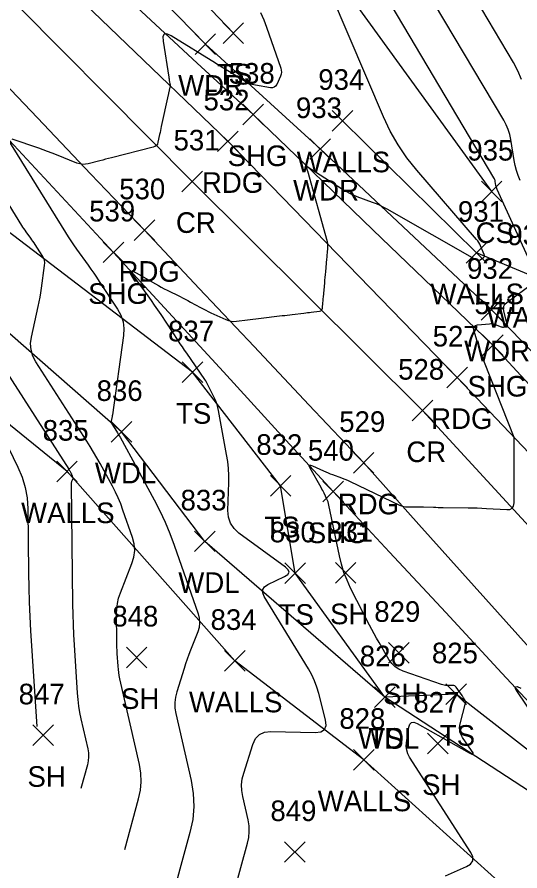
# Model space of a CAD drawing. Extents: x 1592612 to 1596497, y 111838 to 113741.
# Drawn here: x 1592673.5 to 1592722.3, y 113548.4 to 113631.2 of the extents above; entities that cross this region are included whole.
import ezdxf

# ---------------------------------------------------------------- set-up
doc = ezdxf.new("R2010")
doc.units = 0
for name, color, linetype in [('L_A', 7, 'Continuous'), ('L_I', 7, 'Continuous'), ('L_TIC', 7, 'Continuous'), ('LAWA', 7, 'Continuous'), ('LELB', 7, 'Continuous'), ('LSOGCMA', 7, 'Continuous'), ('LSOGCMI', 7, 'Continuous'), ('LWS', 7, 'Continuous'), ('P_A', 7, 'Continuous'), ('P_I', 7, 'Continuous'), ('P_TIC', 7, 'Continuous'), ('PEU', 7, 'Continuous'), ('PRC', 7, 'Continuous'), ('PSU', 7, 'Continuous')]:
    doc.layers.add(name, color=color, linetype=linetype)

msp = doc.modelspace()

# ---------------------------------------------------------------- linework, layer by layer
at = {"layer": 'L_TIC'}
for points in [[(1592693.494, 113628.695), (1592695.494, 113630.695)], [(1592695.494, 113628.695), (1592693.494, 113630.695)], [(1592690.78, 113627.612), (1592692.78, 113629.612)], [(1592692.78, 113627.612), (1592690.78, 113629.612)], [(1592704.094, 113620.183), (1592706.094, 113622.183)], [(1592706.094, 113620.183), (1592704.094, 113622.183)], [(1592701.926, 113617.445), (1592703.926, 113619.445)], [(1592703.926, 113617.445), (1592701.926, 113619.445)], [(1592718.548, 113613.319), (1592720.548, 113615.319)], [(1592720.548, 113613.319), (1592718.548, 113615.319)], [(1592717.067, 113607.381), (1592719.067, 113609.381)], [(1592719.067, 113607.381), (1592717.067, 113609.381)], [(1592718.52, 113601.847), (1592720.52, 113603.847)], [(1592720.52, 113601.847), (1592718.52, 113603.847)], [(1592689.53, 113595.781), (1592691.53, 113597.781)], [(1592691.53, 113595.781), (1592689.53, 113597.781)], [(1592682.654, 113589.995), (1592684.654, 113591.995)], [(1592684.654, 113589.995), (1592682.654, 113591.995)], [(1592677.365, 113586.138), (1592679.365, 113588.138)], [(1592679.365, 113586.138), (1592677.365, 113588.138)], [(1592698.083, 113584.764), (1592700.083, 113586.764)], [(1592700.083, 113584.764), (1592698.083, 113586.764)], [(1592690.74, 113579.372), (1592692.74, 113581.372)], [(1592692.74, 113579.372), (1592690.74, 113581.372)], [(1592704.388, 113576.328), (1592706.388, 113578.328)], [(1592706.388, 113576.328), (1592704.388, 113578.328)], [(1592699.479, 113576.276), (1592701.479, 113578.276)], [(1592701.479, 113576.276), (1592699.479, 113578.276)], [(1592684.119, 113568.111), (1592686.119, 113570.111)], [(1592686.119, 113568.111), (1592684.119, 113570.111)], [(1592709.532, 113568.559), (1592711.532, 113570.559)], [(1592711.532, 113568.559), (1592709.532, 113570.559)], [(1592693.649, 113567.778), (1592695.649, 113569.778)], [(1592695.649, 113567.778), (1592693.649, 113569.778)], [(1592708.175, 113564.248), (1592710.175, 113566.248)], [(1592710.175, 113564.248), (1592708.175, 113566.248)], [(1592708.175, 113564.248), (1592710.175, 113566.248)], [(1592710.175, 113564.248), (1592708.175, 113566.248)], [(1592715.113, 113564.54), (1592717.113, 113566.54)], [(1592717.113, 113564.54), (1592715.113, 113566.54)], [(1592675.039, 113560.553), (1592677.039, 113562.553)], [(1592677.039, 113560.553), (1592675.039, 113562.553)], [(1592713.314, 113559.755), (1592715.314, 113561.755)], [(1592715.314, 113559.755), (1592713.314, 113561.755)], [(1592706.136, 113558.182), (1592708.136, 113560.182)], [(1592708.136, 113558.182), (1592706.136, 113560.182)], [(1592699.459, 113549.229), (1592701.459, 113551.229)], [(1592701.459, 113549.229), (1592699.459, 113551.229)]]:
    msp.add_lwpolyline(points, dxfattribs=at)
at = {"layer": 'LAWA'}
for points in [[(1592820.851, 113504.774), (1592798.01, 113529.796), (1592767.974, 113554.756), (1592744.7, 113575.871), (1592731.754, 113590.187), (1592719.52, 113602.847), (1592702.926, 113618.445), (1592691.78, 113628.612), (1592676.133, 113644.708)], [(1592820.49, 113445.204), (1592799.578, 113454.201), (1592791.672, 113482.437), (1592778.021, 113504.51), (1592763.403, 113519.793), (1592739.369, 113545.558), (1592709.175, 113565.248), (1592691.74, 113580.372), (1592683.654, 113590.995), (1592666.454, 113606.066), (1592652.114, 113621.499)]]:
    msp.add_lwpolyline(points, dxfattribs=at)
at = {"layer": 'LELB'}
for points in [[(1592694.495, 113629.695), (1592678.129, 113646.865)], [(1592719.548, 113614.319), (1592703.53, 113636.472), (1592688.885, 113647.056)], [(1592727.219, 113556.873), (1592716.113, 113565.54), (1592709.175, 113565.248), (1592700.479, 113577.276), (1592699.083, 113585.764), (1592690.53, 113596.781), (1592671.27, 113611.482), (1592656.68, 113625.229)]]:
    msp.add_lwpolyline(points, dxfattribs=at)
at = {"layer": 'LSOGCMA'}
for points in [[(1592722.434, 113625.185), (1592722.084, 113626.025), (1592721.654, 113626.835), (1592717.963, 113633.064)], [(1592683.961, 113550.458), (1592685.313, 113555.397), (1592685.486, 113556.221), (1592685.556, 113557.048), (1592685.523, 113557.877), (1592685.385, 113558.708), (1592683.492, 113567.043), (1592683.43, 113567.344), (1592683.38, 113567.647), (1592683.342, 113567.951), (1592683.316, 113568.257), (1592683.237, 113569.484), (1592683.219, 113569.791), (1592683.206, 113570.098), (1592683.196, 113570.405), (1592683.191, 113570.713), (1592683.161, 113573.301), (1592683.18, 113573.83), (1592683.25, 113574.35), (1592683.37, 113574.861), (1592683.541, 113575.362), (1592684.666, 113578.209), (1592684.856, 113578.842), (1592684.928, 113579.477), (1592684.882, 113580.115), (1592684.718, 113580.755), (1592683.793, 113583.411), (1592683.574, 113584.001), (1592683.332, 113584.581), (1592683.065, 113585.151), (1592682.775, 113585.71), (1592681.569, 113587.927), (1592681.263, 113588.478), (1592680.946, 113589.023), (1592680.62, 113589.563), (1592680.284, 113590.097), (1592675.345, 113597.791), (1592675.051, 113598.356), (1592674.882, 113598.944), (1592674.837, 113599.554), (1592674.916, 113600.187), (1592675.568, 113603.156), (1592675.661, 113603.603), (1592675.746, 113604.051), (1592675.822, 113604.501), (1592675.89, 113604.952), (1592676.193, 113607.124), (1592676.208, 113607.39), (1592676.175, 113607.645), (1592676.095, 113607.889), (1592675.968, 113608.123), (1592675.273, 113609.179), (1592675.169, 113609.336), (1592675.063, 113609.491), (1592674.955, 113609.645), (1592674.846, 113609.798), (1592674.405, 113610.407), (1592674.296, 113610.561), (1592674.19, 113610.716), (1592674.087, 113610.873), (1592673.987, 113611.032), (1592670.021, 113617.466)]]:
    msp.add_lwpolyline(points, dxfattribs=at)
at = {"layer": 'LSOGCMI'}
for points in [[(1592723.532, 113606.897), (1592720.074, 113614.523), (1592720.037, 113614.613), (1592720.006, 113614.705), (1592719.981, 113614.798), (1592719.963, 113614.894), (1592719.9, 113615.279), (1592719.881, 113615.373), (1592719.852, 113615.465), (1592719.815, 113615.554), (1592719.77, 113615.639), (1592708.062, 113635.402)], [(1592722.305, 113615.391), (1592722.11, 113615.861), (1592721.948, 113616.341), (1592721.818, 113616.831), (1592721.721, 113617.331), (1592721.395, 113619.349), (1592721.292, 113619.845), (1592721.143, 113620.325), (1592720.95, 113620.789), (1592720.712, 113621.237), (1592713.013, 113634.233)], [(1592692.448, 113538.57), (1592695.874, 113551.086), (1592695.993, 113551.649), (1592696.041, 113552.215), (1592696.018, 113552.782), (1592695.924, 113553.35), (1592695.407, 113555.627), (1592695.315, 113556.195), (1592695.3, 113556.76), (1592695.361, 113557.321), (1592695.497, 113557.88), (1592696.373, 113560.67), (1592696.636, 113561.237), (1592697.02, 113561.637), (1592697.522, 113561.87), (1592698.144, 113561.935), (1592702.436, 113561.821), (1592702.99, 113561.885), (1592703.34, 113562.113), (1592703.486, 113562.504), (1592703.428, 113563.059), (1592702.787, 113565.605), (1592702.604, 113566.232), (1592702.376, 113566.84), (1592702.102, 113567.429), (1592701.783, 113567.999), (1592697.497, 113575.016), (1592697.342, 113575.377), (1592697.348, 113575.691), (1592697.514, 113575.957), (1592697.841, 113576.176), (1592699.468, 113576.956), (1592699.779, 113577.159), (1592699.896, 113577.381), (1592699.821, 113577.621), (1592699.554, 113577.878), (1592695.041, 113581.178), (1592694.561, 113581.616), (1592694.223, 113582.125), (1592694.028, 113582.704), (1592693.976, 113583.353), (1592694.054, 113586.089), (1592694.056, 113586.771), (1592694.021, 113587.451), (1592693.952, 113588.128), (1592693.846, 113588.802), (1592693.067, 113593.058), (1592693.003, 113593.353), (1592692.919, 113593.641), (1592692.816, 113593.923), (1592692.693, 113594.198), (1592692.026, 113595.57), (1592691.96, 113595.699), (1592691.889, 113595.826), (1592691.814, 113595.949), (1592691.734, 113596.07), (1592689.973, 113598.626), (1592689.763, 113598.933), (1592689.554, 113599.241), (1592689.347, 113599.55), (1592689.142, 113599.861), (1592687.481, 113602.385), (1592687.174, 113602.846), (1592686.862, 113603.304), (1592686.544, 113603.758), (1592686.222, 113604.209), (1592684.82, 113606.146), (1592684.63, 113606.447), (1592684.611, 113606.596), (1592684.76, 113606.591), (1592685.079, 113606.432), (1592686.94, 113605.349), (1592687.222, 113605.188), (1592687.507, 113605.032), (1592687.794, 113604.88), (1592688.084, 113604.733), (1592689.325, 113604.117), (1592689.576, 113603.99), (1592689.827, 113603.861), (1592690.076, 113603.73), (1592690.324, 113603.596), (1592691.313, 113603.056), (1592691.562, 113602.923), (1592691.812, 113602.794), (1592692.065, 113602.671), (1592692.321, 113602.551), (1592693.763, 113601.893), (1592694.012, 113601.799), (1592694.266, 113601.741), (1592694.525, 113601.719), (1592694.79, 113601.733), (1592695.862, 113601.862), (1592696.13, 113601.895), (1592696.398, 113601.927), (1592696.666, 113601.959), (1592696.934, 113601.992), (1592699.226, 113602.271), (1592699.473, 113602.301), (1592699.719, 113602.331), (1592699.965, 113602.361), (1592700.212, 113602.391), (1592701.335, 113602.527), (1592701.513, 113602.548), (1592701.69, 113602.57), (1592701.868, 113602.591), (1592702.046, 113602.613), (1592702.846, 113602.711), (1592702.964, 113602.742), (1592703.051, 113602.802), (1592703.108, 113602.891), (1592703.135, 113603.01), (1592703.182, 113603.542), (1592703.194, 113603.675), (1592703.206, 113603.808), (1592703.218, 113603.941), (1592703.23, 113604.074), (1592703.357, 113605.472), (1592703.38, 113605.731), (1592703.404, 113605.99), (1592703.427, 113606.25), (1592703.451, 113606.509), (1592703.566, 113607.791), (1592703.578, 113607.928), (1592703.591, 113608.065), (1592703.603, 113608.202), (1592703.616, 113608.339), (1592703.667, 113608.888), (1592703.673, 113609.024), (1592703.667, 113609.16), (1592703.649, 113609.294), (1592703.618, 113609.427), (1592701.708, 113616.285), (1592701.693, 113616.338), (1592701.679, 113616.392), (1592701.665, 113616.445), (1592701.651, 113616.499), (1592701.597, 113616.714), (1592701.591, 113616.757), (1592701.6, 113616.779), (1592701.624, 113616.781), (1592701.663, 113616.761), (1592705.081, 113614.55), (1592705.418, 113614.345), (1592705.764, 113614.159), (1592706.12, 113613.992), (1592706.485, 113613.843), (1592707.966, 113613.289), (1592708.333, 113613.143), (1592708.693, 113612.983), (1592709.047, 113612.809), (1592709.394, 113612.621), (1592718.11, 113607.671), (1592718.194, 113607.636), (1592718.276, 113607.627), (1592718.357, 113607.645), (1592718.437, 113607.689), (1592718.753, 113607.916), (1592718.817, 113607.977), (1592718.852, 113608.046), (1592718.858, 113608.123), (1592718.834, 113608.208), (1592718.468, 113609.053), (1592718.388, 113609.22), (1592718.296, 113609.379), (1592718.193, 113609.531), (1592718.077, 113609.676), (1592712.279, 113616.394), (1592711.323, 113617.592), (1592710.468, 113618.852), (1592709.713, 113620.176), (1592709.059, 113621.562), (1592704.014, 113633.413)], [(1592697.138, 113631.696), (1592697.438, 113630.988), (1592697.707, 113630.266), (1592699.087, 113626.3), (1592699.138, 113626.098), (1592699.149, 113625.897), (1592699.12, 113625.698), (1592699.052, 113625.501), (1592698.698, 113624.715), (1592698.594, 113624.548), (1592698.459, 113624.438), (1592698.293, 113624.387), (1592698.097, 113624.394), (1592696.642, 113624.642), (1592696.334, 113624.71), (1592696.036, 113624.806), (1592695.75, 113624.93), (1592695.474, 113625.083), (1592693.699, 113626.181), (1592693.465, 113626.326), (1592693.231, 113626.471), (1592692.998, 113626.616), (1592692.764, 113626.76), (1592688.468, 113629.422), (1592688.057, 113629.614), (1592687.789, 113629.59), (1592687.664, 113629.352), (1592687.681, 113628.9), (1592688.231, 113625.42), (1592688.245, 113625.336), (1592688.258, 113625.251), (1592688.272, 113625.167), (1592688.285, 113625.082), (1592688.358, 113624.627), (1592688.361, 113624.601), (1592688.361, 113624.575), (1592688.359, 113624.549), (1592688.355, 113624.523), (1592688.332, 113624.42), (1592688.321, 113624.368), (1592688.309, 113624.316), (1592688.234, 113623.966), (1592688.22, 113623.899), (1592688.205, 113623.832), (1592688.191, 113623.765), (1592688.176, 113623.698), (1592687.509, 113620.621), (1592687.468, 113620.43), (1592687.427, 113620.24), (1592687.386, 113620.049), (1592687.346, 113619.859), (1592687.184, 113619.097), (1592687.125, 113618.924), (1592687.029, 113618.787), (1592686.896, 113618.686), (1592686.726, 113618.62), (1592682.674, 113617.587), (1592682.393, 113617.516), (1592682.113, 113617.444), (1592681.833, 113617.372), (1592681.552, 113617.299), (1592680.431, 113617.008), (1592680.152, 113616.958), (1592679.876, 113616.953), (1592679.603, 113616.993), (1592679.333, 113617.079), (1592677.335, 113617.88), (1592676.912, 113618.046), (1592676.486, 113618.207), (1592676.058, 113618.363), (1592675.629, 113618.513), (1592673.031, 113619.401)], [(1592672.541, 113619.533), (1592678.211, 113610.334), (1592678.467, 113609.927), (1592678.73, 113609.526), (1592679, 113609.129), (1592679.279, 113608.737), (1592680.406, 113607.181), (1592680.685, 113606.79), (1592680.96, 113606.396), (1592681.231, 113605.999), (1592681.498, 113605.599), (1592683.273, 113602.901), (1592683.597, 113602.304), (1592683.8, 113601.68), (1592683.884, 113601.029), (1592683.847, 113600.351), (1592682.771, 113592.641), (1592682.759, 113592.566), (1592682.747, 113592.492), (1592682.733, 113592.417), (1592682.717, 113592.344), (1592682.653, 113592.049), (1592682.643, 113591.976), (1592682.649, 113591.906), (1592682.668, 113591.839), (1592682.702, 113591.774), (1592683.164, 113591.053), (1592683.254, 113590.911), (1592683.341, 113590.768), (1592683.425, 113590.622), (1592683.506, 113590.476), (1592686.812, 113584.403), (1592687.367, 113583.332), (1592687.877, 113582.241), (1592688.342, 113581.13), (1592688.761, 113579.999), (1592691.076, 113573.349), (1592691.19, 113572.903), (1592691.222, 113572.46), (1592691.172, 113572.018), (1592691.04, 113571.577), (1592690.346, 113569.819), (1592690.176, 113569.379), (1592690.015, 113568.935), (1592689.861, 113568.488), (1592689.716, 113568.039), (1592689.008, 113565.783), (1592688.879, 113565.255), (1592688.822, 113564.724), (1592688.836, 113564.191), (1592688.922, 113563.654), (1592690.399, 113557.153), (1592690.608, 113555.892), (1592690.659, 113554.634), (1592690.553, 113553.38), (1592690.289, 113552.13), (1592688.204, 113544.514)], [(1592666.717, 113605.788), (1592678.528, 113587.389), (1592678.556, 113587.344), (1592678.584, 113587.298), (1592678.611, 113587.252), (1592678.637, 113587.205), (1592678.739, 113587.017), (1592678.764, 113586.97), (1592678.786, 113586.922), (1592678.807, 113586.872), (1592678.826, 113586.822), (1592678.904, 113586.597), (1592678.918, 113586.543), (1592678.922, 113586.489), (1592678.916, 113586.435), (1592678.9, 113586.381), (1592678.814, 113586.164), (1592678.795, 113586.109), (1592678.782, 113586.053), (1592678.774, 113585.997), (1592678.772, 113585.939), (1592678.904, 113574.273), (1592678.922, 113573.282), (1592678.953, 113572.292), (1592678.997, 113571.303), (1592679.054, 113570.314), (1592679.355, 113565.64), (1592679.408, 113565.012), (1592679.486, 113564.388), (1592679.588, 113563.767), (1592679.715, 113563.15), (1592680.378, 113560.232), (1592680.442, 113559.846), (1592680.458, 113559.461), (1592680.425, 113559.077), (1592680.345, 113558.695), (1592679.717, 113556.401)], [(1592715.053, 113547.929), (1592717.098, 113548.809), (1592717.508, 113549.06), (1592717.715, 113549.373), (1592717.719, 113549.749), (1592717.52, 113550.186), (1592711.589, 113559.424), (1592711.416, 113559.753), (1592711.309, 113560.095), (1592711.268, 113560.452), (1592711.293, 113560.823), (1592711.528, 113562.333), (1592711.621, 113562.64), (1592711.782, 113562.805), (1592712.012, 113562.829), (1592712.311, 113562.712), (1592717.374, 113559.845), (1592717.634, 113559.721), (1592717.758, 113559.72), (1592717.746, 113559.844), (1592717.597, 113560.091), (1592716.722, 113561.336), (1592716.547, 113561.647), (1592716.449, 113561.971), (1592716.428, 113562.308), (1592716.484, 113562.66), (1592717.01, 113564.674), (1592717.021, 113564.742), (1592717.018, 113564.808), (1592717.002, 113564.872), (1592716.971, 113564.933), (1592716.809, 113565.193), (1592716.776, 113565.245), (1592716.743, 113565.296), (1592716.71, 113565.348), (1592716.676, 113565.399), (1592716.119, 113566.227), (1592716.055, 113566.303), (1592715.979, 113566.358), (1592715.891, 113566.39), (1592715.792, 113566.4), (1592715.197, 113566.395), (1592715.064, 113566.4), (1592714.932, 113566.416), (1592714.803, 113566.443), (1592714.675, 113566.481), (1592710.969, 113567.767), (1592710.544, 113567.955), (1592710.172, 113568.208), (1592709.853, 113568.525), (1592709.587, 113568.906), (1592708.63, 113570.56), (1592708.393, 113570.975), (1592708.162, 113571.392), (1592707.936, 113571.813), (1592707.715, 113572.237), (1592705.871, 113575.84), (1592705.517, 113576.592), (1592705.217, 113577.362), (1592704.971, 113578.151), (1592704.777, 113578.959), (1592703.771, 113583.893), (1592703.736, 113584.043), (1592703.691, 113584.19), (1592703.637, 113584.334), (1592703.574, 113584.476), (1592703.303, 113585.034), (1592703.234, 113585.172), (1592703.163, 113585.31), (1592703.089, 113585.447), (1592703.013, 113585.582), (1592701.94, 113587.46), (1592701.851, 113587.656), (1592701.859, 113587.762), (1592701.965, 113587.779), (1592702.167, 113587.707), (1592703.252, 113587.203), (1592703.464, 113587.107), (1592703.677, 113587.016), (1592703.892, 113586.93), (1592704.109, 113586.848), (1592704.981, 113586.53), (1592705.198, 113586.448), (1592705.413, 113586.36), (1592705.626, 113586.268), (1592705.836, 113586.17), (1592710.62, 113583.878), (1592710.8, 113583.804), (1592710.985, 113583.752), (1592711.175, 113583.722), (1592711.369, 113583.715), (1592712.157, 113583.728), (1592712.354, 113583.73), (1592712.551, 113583.729), (1592712.748, 113583.726), (1592712.945, 113583.72), (1592713.917, 113583.685), (1592714.144, 113583.678), (1592714.372, 113583.671), (1592714.599, 113583.667), (1592714.827, 113583.663), (1592717.26, 113583.635), (1592717.705, 113583.627), (1592718.15, 113583.614), (1592718.594, 113583.594), (1592719.039, 113583.57), (1592721.018, 113583.447), (1592721.319, 113583.472), (1592721.536, 113583.588), (1592721.668, 113583.795), (1592721.716, 113584.094), (1592721.736, 113585.473), (1592721.74, 113585.817), (1592721.742, 113586.162), (1592721.743, 113586.507), (1592721.741, 113586.851), (1592721.721, 113590.424), (1592721.72, 113590.452), (1592721.72, 113590.459), (1592721.719, 113590.464), (1592718.843, 113597.719), (1592718.708, 113598.072), (1592718.58, 113598.427), (1592718.459, 113598.785), (1592718.347, 113599.146), (1592717.83, 113600.865), (1592717.799, 113601.067), (1592717.845, 113601.218), (1592717.967, 113601.318), (1592718.164, 113601.368), (1592719.325, 113601.491), (1592719.45, 113601.498), (1592719.574, 113601.489), (1592719.695, 113601.467), (1592719.815, 113601.43), (1592720.385, 113601.217), (1592720.457, 113601.194), (1592720.53, 113601.178), (1592720.604, 113601.169), (1592720.679, 113601.167), (1592720.984, 113601.172), (1592721.048, 113601.183), (1592721.088, 113601.211), (1592721.104, 113601.257), (1592721.096, 113601.322), (1592720.722, 113602.723), (1592720.689, 113602.968), (1592720.727, 113603.189), (1592720.835, 113603.384), (1592721.015, 113603.555), (1592723.644, 113605.489)], [(1592671.733, 113591.375), (1592673.598, 113587.56), (1592674.007, 113586.593), (1592674.303, 113585.599), (1592674.485, 113584.578), (1592674.554, 113583.53), (1592674.625, 113577.277), (1592674.65, 113575.881), (1592674.693, 113574.486), (1592674.755, 113573.092), (1592674.836, 113571.698), (1592675.434, 113562.398)], [(1592723.653, 113563.371), (1592722.044, 113565.765), (1592721.864, 113566.086), (1592721.859, 113566.255), (1592722.027, 113566.274), (1592722.37, 113566.141)]]:
    msp.add_lwpolyline(points, dxfattribs=at)
at = {"layer": 'LWS'}
for points in [[(1592723.518, 113606.111), (1592718.067, 113608.381), (1592705.094, 113621.183)], [(1592776.94, 113499.802), (1592759.191, 113514.391), (1592732.196, 113536.522), (1592707.136, 113559.182), (1592694.649, 113568.778), (1592678.365, 113587.138), (1592659.477, 113602.479)]]:
    msp.add_lwpolyline(points, dxfattribs=at)
at = {"layer": 'P_TIC'}
for points in [[(1592695.408, 113620.785), (1592697.408, 113622.785)], [(1592697.408, 113620.785), (1592695.408, 113622.785)], [(1592692.964, 113618.189), (1592694.964, 113620.189)], [(1592694.964, 113618.189), (1592692.964, 113620.189)], [(1592689.495, 113614.302), (1592691.495, 113616.302)], [(1592691.495, 113614.302), (1592689.495, 113616.302)], [(1592684.878, 113609.564), (1592686.878, 113611.564)], [(1592686.878, 113609.564), (1592684.878, 113611.564)], [(1592681.884, 113607.415), (1592683.884, 113609.415)], [(1592683.884, 113607.415), (1592681.884, 113609.415)], [(1592718.668, 113598.42), (1592720.668, 113600.42)], [(1592720.668, 113598.42), (1592718.668, 113600.42)], [(1592715.192, 113595.277), (1592717.192, 113597.277)], [(1592717.192, 113595.277), (1592715.192, 113597.277)], [(1592711.839, 113592.062), (1592713.839, 113594.062)], [(1592713.839, 113592.062), (1592711.839, 113594.062)], [(1592706.134, 113586.991), (1592708.134, 113588.991)], [(1592708.134, 113586.991), (1592706.134, 113588.991)], [(1592703.178, 113584.201), (1592705.178, 113586.201)], [(1592705.178, 113584.201), (1592703.178, 113586.201)]]:
    msp.add_lwpolyline(points, dxfattribs=at)
at = {"layer": 'PEU'}
for points in [[(1592852.273, 113463.849), (1592836.279, 113474.056), (1592819.972, 113487.621), (1592800.662, 113505.499), (1592780.779, 113527.086), (1592759.62, 113549.571), (1592738.37, 113572.943), (1592716.192, 113596.277), (1592693.964, 113619.189), (1592672.676, 113639.672)], [(1592744.662, 113547.12), (1592739.305, 113552.768), (1592733.948, 113558.416), (1592728.591, 113564.063), (1592723.227, 113570.045), (1592717.863, 113576.027), (1592712.498, 113582.009), (1592707.134, 113587.991), (1592701.82, 113593.634), (1592696.506, 113599.278), (1592691.192, 113604.921), (1592685.878, 113610.564), (1592680.686, 113616.008), (1592675.493, 113621.453), (1592670.301, 113626.898), (1592665.108, 113632.343)]]:
    msp.add_lwpolyline(points, dxfattribs=at)
at = {"layer": 'PRC'}
msp.add_lwpolyline([(1592851.008, 113460.149), (1592833.097, 113469.523), (1592815.857, 113483.202), (1592796.573, 113501.275), (1592777.295, 113523.934), (1592756.259, 113546.33), (1592734.615, 113569.346), (1592712.839, 113593.061), (1592690.495, 113615.302), (1592669.477, 113636.459)], dxfattribs=at)
at = {"layer": 'PSU'}
for points in [[(1592674.777, 113641.79), (1592680.185, 113636.789), (1592685.592, 113631.788), (1592691, 113626.787), (1592696.408, 113621.785), (1592702.223, 113616.194), (1592708.038, 113610.602), (1592713.853, 113605.011), (1592719.668, 113599.42), (1592725.129, 113593.479), (1592730.589, 113587.538), (1592736.05, 113581.597), (1592741.511, 113575.656), (1592747.342, 113570.261), (1592753.173, 113564.867), (1592759.003, 113559.472), (1592764.834, 113554.078), (1592770.049, 113548.457), (1592775.263, 113542.835)], [(1592662.695, 113630.145), (1592667.742, 113624.713), (1592672.79, 113619.28), (1592677.837, 113613.848), (1592682.884, 113608.415), (1592688.208, 113602.611), (1592693.531, 113596.808), (1592698.855, 113591.004), (1592704.178, 113585.201), (1592709.634, 113579.332), (1592715.09, 113573.464), (1592720.547, 113567.595), (1592726.003, 113561.726), (1592731.459, 113556.245), (1592736.914, 113550.763), (1592742.37, 113545.281)]]:
    msp.add_lwpolyline(points, dxfattribs=at)

# ---------------------------------------------------------------- texts
at = {"layer": 'L_A'}
for s, p in [('TS', (1592692.904, 113624.695)), ('WDR', (1592689.142, 113623.612)), ('WALLS', (1592700.637, 113616.183)), ('WDR', (1592700.288, 113613.445)), ('CS', (1592717.989, 113609.319)), ('WALLS', (1592713.611, 113603.381)), ('WALLS', (1592719.061, 113601.111)), ('WDR', (1592716.882, 113597.847)), ('TS', (1592688.94, 113591.781)), ('WDL', (1592681.071, 113585.995)), ('WALLS', (1592673.909, 113582.138)), ('TS', (1592697.493, 113580.764)), ('WDL', (1592689.157, 113575.372)), ('TS', (1592698.888, 113572.276)), ('SH', (1592703.876, 113572.328)), ('SH', (1592683.607, 113564.111)), ('SH', (1592709.02, 113564.559)), ('WALLS', (1592690.192, 113563.778)), ('WDL', (1592706.592, 113560.248)), ('TS', (1592707.584, 113560.248)), ('TS', (1592714.522, 113560.54)), ('SH', (1592674.527, 113556.553)), ('SH', (1592712.802, 113555.755)), ('WALLS', (1592702.68, 113554.182))]:
    msp.add_text(s, height=2, dxfattribs=at).set_placement(p)
at = {"layer": 'L_I'}
for s, p in [('934', (1592702.732, 113624.183)), ('933', (1592700.564, 113621.445)), ('935', (1592717.186, 113617.319)), ('931', (1592716.272, 113611.381)), ('930', (1592721.069, 113609.111)), ('932', (1592717.158, 113605.847)), ('837', (1592688.168, 113599.781)), ('836', (1592681.236, 113593.995)), ('835', (1592676.003, 113590.138)), ('832', (1592696.721, 113588.764)), ('833', (1592689.378, 113583.372)), ('830', (1592698.03, 113580.276)), ('831', (1592703.592, 113580.328)), ('829', (1592708.162, 113572.559)), ('848', (1592682.757, 113572.111)), ('834', (1592692.287, 113571.778)), ('826', (1592706.757, 113568.248)), ('826', (1592706.757, 113568.248)), ('825', (1592713.751, 113568.54)), ('847', (1592673.676, 113564.553)), ('827', (1592711.952, 113563.755)), ('828', (1592704.774, 113562.182)), ('849', (1592698.089, 113553.229))]:
    msp.add_text(s, height=2, dxfattribs=at).set_placement(p)
at = {"layer": 'P_A'}
for s, p in [('SHG', (1592693.943, 113616.785)), ('RDG', (1592691.452, 113614.189)), ('CR', (1592688.928, 113610.302)), ('RDG', (1592683.366, 113605.564)), ('SHG', (1592680.42, 113603.415)), ('SHG', (1592717.204, 113594.42)), ('RDG', (1592713.68, 113591.277)), ('CR', (1592711.272, 113588.062)), ('RDG', (1592704.622, 113582.991)), ('SHG', (1592701.714, 113580.201))]:
    msp.add_text(s, height=2, dxfattribs=at).set_placement(p)
at = {"layer": 'P_I'}
for s, p in [('538', (1592694.046, 113624.785)), ('532', (1592691.602, 113622.189)), ('531', (1592688.699, 113618.302)), ('530', (1592683.429, 113613.564)), ('539', (1592680.514, 113611.415)), ('541', (1592717.873, 113602.42)), ('527', (1592713.829, 113599.277)), ('528', (1592710.477, 113596.062)), ('529', (1592704.764, 113590.991)), ('540', (1592701.729, 113588.201))]:
    msp.add_text(s, height=2, dxfattribs=at).set_placement(p)

doc.saveas('drawing.dxf')
